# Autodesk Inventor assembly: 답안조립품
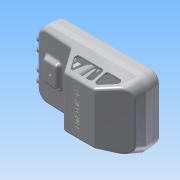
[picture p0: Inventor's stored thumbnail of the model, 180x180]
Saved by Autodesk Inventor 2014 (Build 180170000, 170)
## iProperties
Created: 2015-05
Part Number: 답안조립품
Document SubType Name: Assembly
Designer: Administrator
Author: Administrator
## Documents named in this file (7)
- C:\Documents and Settings\Administrator\바탕 화면\450507V1027\답안조립품.iam
- C:\Documents and Settings\Administrator\바탕 화면\450507V1027\1-본체.ipt
- C:\Documents and Settings\Administrator\바탕 화면\450507V1027\커버.ipt
- C:\Documents and Settings\Administrator\바탕 화면\450507V1027\바퀴.ipt
- C:\Documents and Settings\Administrator\바탕 화면\450507V1027\바퀴고정부.ipt
- C:\Documents and Settings\Administrator\바탕 화면\450507V1027\M4x10.ipt
- C:\Documents and Settings\Administrator\바탕 화면\450507V1027\M2x4.ipt
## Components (21 placed, 3 different names)
1. 1-본체:1
2. M4x10:1
3. M4x10:2
4. M4x10:3
5. M4x10:4
6. M2x4:1
7. M2x4:2
8. M2x4:3
9. M2x4:4
10. M2x4:5
11. M2x4:6
12. M2x4:7
13. M2x4:8
14. M2x4:9
15. M2x4:10
16. M2x4:11
17. M2x4:12
18. M2x4:13
19. M2x4:14
20. M2x4:15
21. M2x4:16
